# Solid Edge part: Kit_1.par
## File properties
Last saved by: bmolnar
Revision: 77
Sűrűség: 0,000 kg/m^3
Pontosság: 0,990
Dokumentum tartalom típus: 0
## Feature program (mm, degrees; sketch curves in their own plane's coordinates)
base feature "unnamed BaseFeature 1"
sketch for "unnamed Cutout 1" plane through (0, -0.0012, 85.05) normal (0, 0, -1) x-axis (-1, 0, 0)
  circle centre (0, 0.0012) radius 6
extrude "unnamed Cutout 1" cut through along -normal
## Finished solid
Body 1: solid body, 48 faces, 65 edges, 51 vertices, 1 internal void.
  Faces by surface: cone 15, cylinder 15, plane 14, torus 4
  Edges by curve: circle 47, line 18
Bounding box of the edges (mm; curved faces can reach further): 35.700 x 35.450 x 9.450, from (-17.85, -16.85, 85.05) to (17.85, 18.6, 94.5).
Cylindrical faces by radius (mm): R1.25 x2, R2.25 x2, R6 x1, R6.27 x1, R6.85 x1, R7 x1, R8.16 x1, R8.25 x1, R11.5 x1, R12.25 x1, R15.9 x1, R16.85 x1, R17.85 x1
Conical faces (half-angle, radius in mm at the cone's reference point): 3 deg R8.205 x1, 7 deg R7.5925 x1, 14 deg R6.135 x1, 14 deg R6.4811 x1, 17 deg R6.135 x1, 23 deg R6.829 x1, 30 deg R11.875 x1, 42.5 deg R6.1233 x1, 45 deg R7.1 x2, 45 deg R11.75 x1, 84 deg R59.397 x2, 85 deg R7.9463 x1, 87 deg R6.1765 x1
Toroidal faces (ring radius, tube radius in mm): R6.8057 r0.2025 x1, R7.2522 r0.2925 x1, R7.96 r0.2 x1, R11.9 r0.4 x1
Planar faces by outward normal: +z 7, -z 3, oblique 4
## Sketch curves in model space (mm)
circle centre (0, 0, 85.05) radius 6
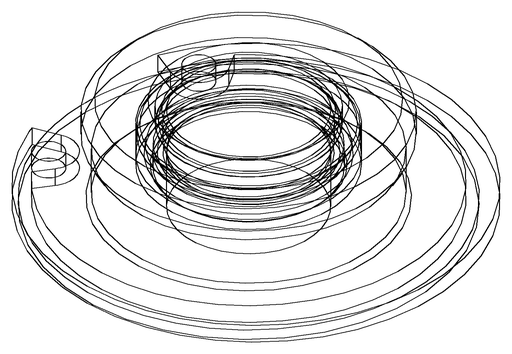
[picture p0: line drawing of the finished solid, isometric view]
